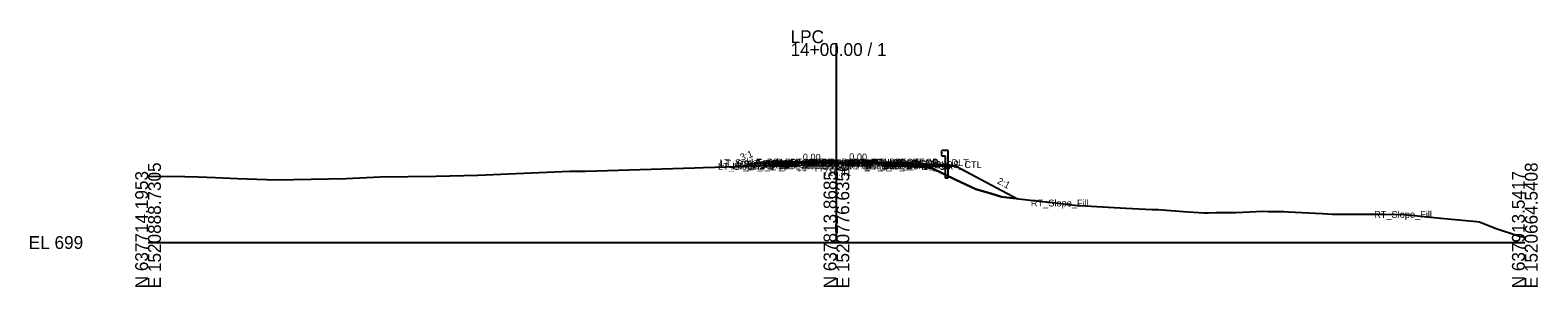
# Model space of a CAD drawing. Extents: x -26 to 303, y -10 to 4521.
# Drawn here: x -25.7 to 302.8, y 3990.3 to 4046.4 of the extents above; entities that cross this region are included whole.
import ezdxf

# ---------------------------------------------------------------- set-up
doc = ezdxf.new("R2010")
doc.units = 0
for name, color, linetype in [('Default', 7, 'Continuous'), ('Exist Cross Section Cell', 7, 'Continuous'), ('Exist XS Center Line Elevation Label', 7, 'Continuous'), ('Exist XS Ground Line', 7, 'Continuous'), ('Prop CMT Guardrail Graphics', 7, 'Continuous'), ('Prop CMT Pvmt Course 1', 7, 'Continuous'), ('Prop CMT Pvmt Course 2', 7, 'Continuous'), ('Prop CMT Pvmt Course 3', 7, 'Continuous'), ('Prop CMT Pvmt Surface', 7, 'Continuous'), ('Prop CMT Pvmt Surface Shoulder', 7, 'Continuous'), ('Prop CMT Shld Paved Course 1', 7, 'Continuous'), ('Prop CMT Shld Paved Course 2', 7, 'Continuous'), ('Prop CMT Shld Paved Course 3', 7, 'Continuous'), ('Prop CMT Slope Grass', 7, 'Continuous'), ('Prop CMT Subgrade Earthwork', 7, 'Continuous'), ('Prop XS Earthwork Shape', 7, 'Continuous'), ('Prop XS Shear Point Element', 7, 'Continuous')]:
    doc.layers.add(name, color=color, linetype=linetype)

msp = doc.modelspace()

# ---------------------------------------------------------------- linework, layer by layer
at = {"layer": 'Exist Cross Section Cell'}
for p, q in [((150, 4000), (150, 4043.53)), ((0, 4000), (150, 4000)), ((150, 4000), (300, 4000))]:
    msp.add_line(p, q, dxfattribs=at)
at = {"layer": 'Exist XS Ground Line'}
msp.add_lwpolyline([(0, 4014.51), (8.03, 4014.39), (10.91, 4014.37), (14.66, 4014.16), (19.5, 4013.94), (27.94, 4013.65), (43.15, 4013.96), (50.57, 4014.35), (62.72, 4014.48), (71.86, 4014.73), (91.91, 4015.58), (92.3, 4015.57), (94.4, 4015.61), (95.39, 4015.61), (119.1, 4016.34), (120.93, 4016.4), (131.18, 4016.65), (137.45, 4017.07), (141.56, 4017.33), (141.98, 4017.34), (143.12, 4017.35), (143.4, 4017.35), (145.02, 4017.37), (146.43, 4017.38), (146.77, 4017.39), (147.15, 4017.39), (149.79, 4017.41), (150, 4017.41), (150.89, 4017.41), (153.06, 4017.41), (154.66, 4017.42), (155.58, 4017.42), (156.42, 4017.42), (157.36, 4017.42), (158.41, 4017.42), (159.38, 4017.42), (159.95, 4017.43), (160.08, 4017.42), (160.84, 4017.42), (161.13, 4017.42), (167.24, 4016.63), (170.8, 4016.2), (176.01, 4013.69), (180.37, 4011.62), (183.61, 4010.69), (185.99, 4009.96), (194.82, 4008.98), (195.68, 4008.87), (196.08, 4008.82), (196.27, 4008.8), (197.12, 4008.74), (202.49, 4008.06), (203.09, 4008.05), (206.72, 4007.88), (213.07, 4007.49), (218.82, 4007.24), (220.12, 4007.19), (225.66, 4006.78), (230.04, 4006.46), (231.07, 4006.45), (232.76, 4006.52), (237, 4006.54), (242.95, 4006.81), (244.16, 4006.8), (245.63, 4006.8), (247.51, 4006.74), (248.45, 4006.69), (255.92, 4006.32), (258.06, 4006.18), (262.85, 4006.22), (266.24, 4006.22), (269.39, 4006.19), (273.73, 4006.11), (280.26, 4005.47), (281.71, 4005.32), (283.2, 4005.17), (289.58, 4004.57), (290.15, 4004.54), (293.55, 4003.15), (298.84, 4001.42), (300, 4001.18)], dxfattribs=at)
at = {"layer": 'Prop CMT Guardrail Graphics'}
for points in [[(174.38, 4020.12), (173.05, 4020.12), (172.78, 4019.82)], [(172.78, 4019.82), (173.05, 4019.53)], [(173.05, 4019.53), (172.78, 4019.24)], [(172.78, 4019.24), (173.05, 4018.95), (173.72, 4018.95)], [(173.72, 4018.95), (173.72, 4014.12)], [(174.38, 4014.12), (174.38, 4020.12)], [(173.72, 4014.12), (174.38, 4014.12)]]:
    msp.add_lwpolyline(points, dxfattribs=at)
at = {"layer": 'Prop CMT Pvmt Course 1'}
msp.add_line((150, 4017.54), (159.95, 4017.54), dxfattribs=at)
for points in [[(150, 4017.54), (141.5, 4017.54)], [(141.5, 4017.54), (141.5, 4017.29)], [(141.5, 4017.29), (150, 4017.29)], [(150, 4017.29), (150, 4017.54)], [(150, 4017.29), (150, 4017.54)], [(159.95, 4017.29), (150, 4017.29)], [(159.95, 4017.54), (159.95, 4017.29)]]:
    msp.add_lwpolyline(points, dxfattribs=at)
msp.add_lwpolyline([(150, 4017.29), (150, 4017.42), (150, 4017.42), (150, 4017.29)], close=True, dxfattribs=at)
msp.add_lwpolyline([(150, 4017.29), (150, 4017.42), (150, 4017.42), (150, 4017.29)], close=True, dxfattribs=at)
at = {"layer": 'Prop CMT Pvmt Course 2'}
for points in [[(150, 4017.29), (141.5, 4017.29)], [(141.5, 4017.29), (141.5, 4016.96)], [(150, 4017.29), (159.95, 4017.29)], [(159.95, 4017.29), (159.95, 4016.96)]]:
    msp.add_lwpolyline(points, dxfattribs=at)
at = {"layer": 'Prop CMT Pvmt Course 3'}
for points in [[(141.5, 4016.96), (141.5, 4016.71)], [(159.95, 4016.96), (159.95, 4016.71)]]:
    msp.add_lwpolyline(points, dxfattribs=at)
at = {"layer": 'Prop CMT Pvmt Surface'}
for points in [[(150, 4017.54), (141.5, 4017.54)], [(150, 4017.54), (159.95, 4017.54)]]:
    msp.add_lwpolyline(points, dxfattribs=at)
at = {"layer": 'Prop CMT Pvmt Surface Shoulder'}
for points in [[(141.5, 4017.54), (137.5, 4017.54)], [(159.95, 4017.54), (163.95, 4017.54)]]:
    msp.add_lwpolyline(points, dxfattribs=at)
at = {"layer": 'Prop CMT Shld Paved Course 1'}
for p in [(164.22, 4017.27), (172.78, 4016.97)]:
    msp.add_line(p, (172.78, 4016.72), dxfattribs=at)
for points in [[(141.5, 4017.54), (137.5, 4017.54), (137.25, 4017.29)], [(137.25, 4017.29), (141.5, 4017.29)], [(141.5, 4017.29), (141.5, 4017.54)], [(159.95, 4017.54), (163.95, 4017.54), (164.2, 4017.29)], [(159.95, 4017.29), (159.95, 4017.54)], [(164.2, 4017.29), (159.95, 4017.29)]]:
    msp.add_lwpolyline(points, dxfattribs=at)
at = {"layer": 'Prop CMT Shld Paved Course 2'}
for points in [[(141.5, 4017.29), (137.25, 4017.29), (136.92, 4016.96)], [(136.92, 4016.96), (141.5, 4016.96)], [(141.5, 4016.96), (141.5, 4017.29)], [(159.95, 4017.29), (164.2, 4017.29), (164.53, 4016.96)], [(159.95, 4016.96), (159.95, 4017.29)], [(164.53, 4016.96), (159.95, 4016.96)]]:
    msp.add_lwpolyline(points, dxfattribs=at)
at = {"layer": 'Prop CMT Shld Paved Course 3'}
for p, q in [((136.92, 4016.96), (136.67, 4016.71)), ((164.53, 4016.96), (164.78, 4016.71))]:
    msp.add_line(p, q, dxfattribs=at)
for points in [[(136.17, 4016.71), (141.5, 4016.71)], [(141.5, 4016.96), (136.92, 4016.96), (136.67, 4016.71)], [(141.5, 4016.71), (141.5, 4016.96)], [(159.95, 4016.71), (159.95, 4016.96)], [(159.95, 4016.96), (164.53, 4016.96), (164.78, 4016.71)], [(165.28, 4016.71), (159.95, 4016.71)]]:
    msp.add_lwpolyline(points, dxfattribs=at)
at = {"layer": 'Prop CMT Slope Grass'}
for points in [[(137.5, 4017.54), (131.5, 4017.18), (129.81, 4016.62)], [(163.95, 4017.54), (175.78, 4016.78), (189.48, 4009.57)]]:
    msp.add_lwpolyline(points, dxfattribs=at)
at = {"layer": 'Prop CMT Subgrade Earthwork'}
msp.add_line((159.95, 4017.29), (141.5, 4017.29), dxfattribs=at)
for points in [[(141.5, 4016.71), (130.09, 4016.71)], [(141.5, 4017.29), (141.5, 4016.71)], [(159.95, 4017.29), (159.95, 4016.71)], [(159.95, 4016.71), (175.91, 4016.71)]]:
    msp.add_lwpolyline(points, dxfattribs=at)
at = {"layer": 'Prop XS Earthwork Shape'}
for points in [[(131.18, 4016.65), (132.06, 4016.71), (130.09, 4016.71), (129.81, 4016.62)], [(132.06, 4016.71), (130.09, 4016.71), (129.81, 4016.62), (131.18, 4016.65)], [(132.06, 4016.71), (130.09, 4016.71), (129.81, 4016.62), (131.18, 4016.65)], [(141.5, 4017.29), (141.5, 4016.71), (132.06, 4016.71), (137.45, 4017.07)], [(141.5, 4016.71), (132.06, 4016.71), (137.45, 4017.07), (141.5, 4017.29)], [(159.95, 4016.71), (166.63, 4016.71), (161.13, 4017.42), (160.84, 4017.42), (160.08, 4017.42), (159.95, 4017.43), (159.38, 4017.42), (158.41, 4017.42), (157.36, 4017.42), (156.42, 4017.42), (155.58, 4017.42), (154.66, 4017.42), (153.06, 4017.41), (150.89, 4017.41), (150, 4017.41), (149.79, 4017.41), (147.15, 4017.39), (146.77, 4017.39), (146.43, 4017.38), (145.02, 4017.37), (143.4, 4017.35), (143.12, 4017.35), (141.98, 4017.34), (141.5, 4017.29), (159.95, 4017.29)], [(175.91, 4016.71), (189.48, 4009.57), (185.99, 4009.96), (183.61, 4010.69), (180.37, 4011.62), (176.01, 4013.69), (170.8, 4016.2), (167.24, 4016.63), (166.63, 4016.71)]]:
    msp.add_lwpolyline(points, close=True, dxfattribs=at)

# ---------------------------------------------------------------- texts
at = {"layer": 'Default'}
msp.add_text('-', height=0.0001, dxfattribs=at).set_placement((0, 4000))
at = {"layer": 'Exist Cross Section Cell'}
for s, p in [('LPC', (140, 4043.53)), ('14+00.00 / 1', (140, 4040.73)), ('EL 699', (-26, 3998.6))]:
    msp.add_text(s, height=2.8, dxfattribs=at).set_placement(p)
for s, p in [('N 637714.1953', (0, 3990)), ('E 1520888.7305', (2.8, 3990)), ('N 637813.8685', (150, 3990)), ('E 1520776.6356', (152.8, 3990)), ('N 637913.5417', (300, 3990)), ('E 1520664.5408', (302.8, 3990))]:
    msp.add_text(s, height=2.8, rotation=90, dxfattribs=at).set_placement(p)
at = {"layer": 'Exist XS Center Line Elevation Label'}
for s, rotation, p in [('3:1', 19.8357, (129.34, 4017.81)), ('0.00', 358.8358, (142.65, 4017.92)), ('0.00', 358.8358, (152.76, 4017.98)), ('2:1', 332.3479, (184.88, 4012.97))]:
    msp.add_text(s, height=1.5, rotation=rotation, dxfattribs=at).set_placement(p)
msp.add_text('716.41', height=1.5, dxfattribs=at).set_placement((147.08, 4014.59))
at = {"layer": 'Prop XS Shear Point Element'}
for s, p in [('LT_Sub_Trench_Out_DLT', (124.44, 4016.67)), ('LT_PS2_OEOP', (130.93, 4016.54)), ('LT_PS1_OEOP', (131.36, 4016.79)), ('LT_PV2_OEOT', (135.12, 4016.54)), ('LT_PV1_OEOT', (135.3, 4016.79)), ('RT_PV2_OEEOP', (143, 4016.54)), ('LT_PV2_OEEOP', (143.09, 4016.54)), ('RT_PV1_OEEOP', (143.18, 4016.67)), ('LT_PV1_OEEOP', (143.27, 4016.67)), ('RT_PV2_IEEOP', (143.57, 4016.54)), ('LT_PV2_IEEOP', (143.66, 4016.54)), ('RT_PV1_IEEOP', (143.75, 4016.67)), ('LT_PV1_IEEOP', (143.84, 4016.67)), ('PV2_PGL', (146.03, 4016.54)), ('PV1_PGL', (146.2, 4016.79)), ('RT_PV2_OEOT', (153.48, 4016.54)), ('RT_PV1_OEOT', (153.66, 4016.79)), ('RT_Sub_Trench_Out_DLT', (154.88, 4016.67)), ('RT_PS1_OEOP', (157.72, 4016.79)), ('RT_PS2_OEOP', (157.79, 4016.54)), ('LT_Slope_Fill', (124.17, 4015.87)), ('LT_GS_OS_CTL', (124.7, 4016.43)), ('LT_Sub_Trench_Out', (127.33, 4015.96)), ('LT_PS3_Shelf_Out', (128.41, 4016.21)), ('LT_PS3_OEOP', (130.6, 4016.21)), ('LT_PV3_OEOT', (135.12, 4016.21)), ('LT_Sub_OEOT', (135.15, 4015.96)), ('RT_PV3_OEEOP', (143, 4016.21)), ('RT_Sub_OEEOP', (143.04, 4015.96)), ('LT_PV3_OEEOP', (143.09, 4016.21)), ('LT_Sub_OEEOP', (143.12, 4015.96)), ('RT_PV3_OEOT', (153.48, 4016.21)), ('RT_Sub_OEOT', (153.52, 4015.96)), ('RT_Sub_Trench_Out', (156.36, 4015.96)), ('RT_PS3_Shelf_Out', (156.93, 4016.21)), ('RT_PS3_OEOP', (158.12, 4016.21)), ('RT_GS_OS_CTL', (166.06, 4016.25)), ('RT_Slope_Fill', (192.37, 4007.87)), ('RT_Slope_Fill', (267.16, 4005.38))]:
    msp.add_text(s, height=1.5, dxfattribs=at).set_placement(p)

doc.saveas('drawing.dxf')
